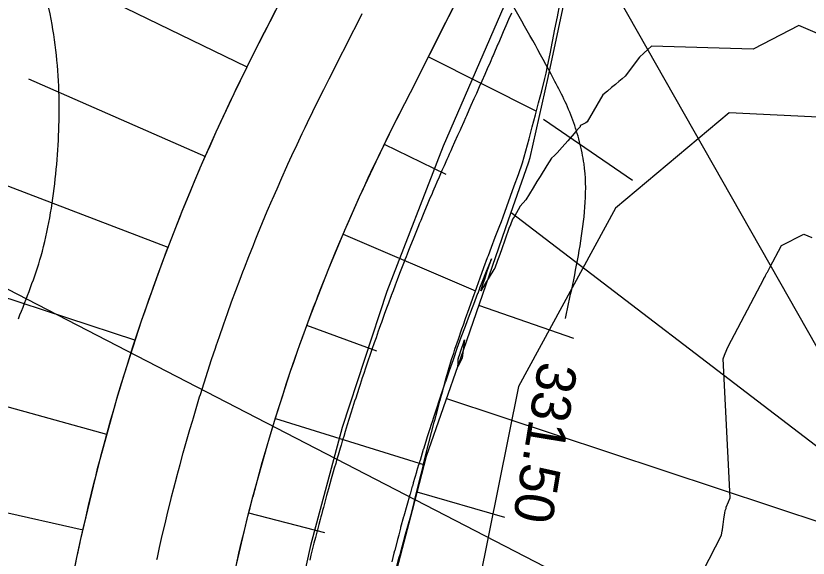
# Model space of a CAD drawing. Extents: x -564037 to -563827, y -1163561 to -1163412.
# Drawn here: x -563866.4 to -563856.32, y -1163500.35 to -1163493.46 of the extents above; entities that cross this region are included whole.
import ezdxf

# ---------------------------------------------------------------- set-up
doc = ezdxf.new("R2010")
doc.units = 0
for name, color, linetype in [('5', 7, 'Continuous'), ('Default', 7, 'Continuous'), ('Line', 7, 'Continuous'), ('Vrstva 24', 7, 'Continuous'), ('Vrstva 25', 7, 'Continuous'), ('Vrstva 26', 7, 'Continuous')]:
    doc.layers.add(name, color=color, linetype=linetype)

msp = doc.modelspace()

# ---------------------------------------------------------------- linework, layer by layer
for points in [[(-563865.785, -1163501.206), (-563865.619, -1163500.343), (-563865.574, -1163500.129), (-563865.385, -1163499.33), (-563865.317, -1163499.063), (-563865.111, -1163498.327), (-563865.015, -1163498.009), (-563864.797, -1163497.335), (-563864.669, -1163496.968), (-563864.528, -1163496.58), (-563864.443, -1163496.357), (-563864.28, -1163495.943), (-563864.051, -1163495.394), (-563863.848, -1163494.935), (-563863.62, -1163494.448), (-563863.373, -1163493.946), (-563863.165, -1163493.533), (-563862.713, -1163492.641), (-563862.262, -1163491.749), (-563861.987, -1163491.206), (-563861.81, -1163490.857), (-563861.359, -1163489.964), (-563861.279, -1163489.807)], [(-563863.62, -1163500.557), (-563863.446, -1163499.819), (-563863.383, -1163499.573), (-563863.193, -1163498.893), (-563863.104, -1163498.599), (-563862.903, -1163497.978), (-563862.785, -1163497.638), (-563862.654, -1163497.28), (-563862.576, -1163497.075), (-563862.426, -1163496.692), (-563862.214, -1163496.186), (-563862.026, -1163495.761), (-563861.817, -1163495.312), (-563861.589, -1163494.849), (-563861.38, -1163494.436), (-563860.928, -1163493.544), (-563860.477, -1163492.652), (-563860.202, -1163492.109), (-563860.026, -1163491.76), (-563859.574, -1163490.867), (-563859.495, -1163490.71)], [(-563865.645, -1163500.469), (-563865.619, -1163500.343), (-563865.613, -1163500.311), (-563865.579, -1163500.154), (-563865.574, -1163500.129), (-563865.544, -1163499.997), (-563865.508, -1163499.84), (-563865.472, -1163499.683), (-563865.434, -1163499.526), (-563865.395, -1163499.37), (-563865.385, -1163499.33), (-563865.356, -1163499.214), (-563865.317, -1163499.063), (-563865.315, -1163499.058), (-563865.274, -1163498.902), (-563865.231, -1163498.747), (-563865.188, -1163498.592), (-563865.143, -1163498.437), (-563865.111, -1163498.327), (-563865.098, -1163498.283), (-563865.052, -1163498.128), (-563865.015, -1163498.009), (-563865.004, -1163497.974), (-563864.956, -1163497.821), (-563864.907, -1163497.667), (-563864.857, -1163497.514), (-563864.806, -1163497.362), (-563864.797, -1163497.335), (-563864.754, -1163497.209), (-563864.701, -1163497.057), (-563864.669, -1163496.968), (-563864.647, -1163496.905), (-563864.592, -1163496.754), (-563864.536, -1163496.603), (-563864.48, -1163496.452), (-563864.443, -1163496.357), (-563864.422, -1163496.302), (-563864.363, -1163496.152), (-563864.304, -1163496.002), (-563864.28, -1163495.943), (-563864.243, -1163495.853), (-563864.182, -1163495.704), (-563864.12, -1163495.555), (-563864.056, -1163495.407), (-563864.051, -1163495.394), (-563863.992, -1163495.259), (-563863.927, -1163495.112), (-563863.861, -1163494.965), (-563863.848, -1163494.935), (-563863.795, -1163494.819), (-563863.727, -1163494.673), (-563863.658, -1163494.527), (-563863.62, -1163494.448), (-563863.589, -1163494.382), (-563863.518, -1163494.237), (-563863.447, -1163494.092), (-563863.374, -1163493.948), (-563863.373, -1163493.946), (-563863.305, -1163493.81), (-563863.235, -1163493.672), (-563863.165, -1163493.533), (-563863.095, -1163493.396)], [(-563863.593, -1163500.434), (-563863.56, -1163500.289), (-563863.526, -1163500.144), (-563863.491, -1163500), (-563863.455, -1163499.856), (-563863.446, -1163499.819), (-563863.419, -1163499.711), (-563863.383, -1163499.573), (-563863.381, -1163499.568), (-563863.343, -1163499.424), (-563863.304, -1163499.281), (-563863.264, -1163499.137), (-563863.223, -1163498.995), (-563863.193, -1163498.893), (-563863.181, -1163498.852), (-563863.138, -1163498.71), (-563863.104, -1163498.599), (-563863.094, -1163498.567), (-563863.05, -1163498.426), (-563863.004, -1163498.284), (-563862.958, -1163498.143), (-563862.911, -1163498.002), (-563862.903, -1163497.978), (-563862.863, -1163497.861), (-563862.814, -1163497.721), (-563862.785, -1163497.638), (-563862.764, -1163497.581), (-563862.714, -1163497.441), (-563862.662, -1163497.301), (-563862.61, -1163497.162), (-563862.576, -1163497.075), (-563862.557, -1163497.023), (-563862.503, -1163496.885), (-563862.448, -1163496.747), (-563862.426, -1163496.692), (-563862.392, -1163496.609), (-563862.335, -1163496.472), (-563862.278, -1163496.334), (-563862.219, -1163496.198), (-563862.214, -1163496.186), (-563862.16, -1163496.061), (-563862.1, -1163495.925), (-563862.039, -1163495.79), (-563862.026, -1163495.761), (-563861.978, -1163495.654), (-563861.915, -1163495.52), (-563861.852, -1163495.385), (-563861.817, -1163495.312), (-563861.787, -1163495.251), (-563861.722, -1163495.117), (-563861.657, -1163494.984), (-563861.59, -1163494.851), (-563861.589, -1163494.849), (-563861.52, -1163494.713), (-563861.45, -1163494.575), (-563861.38, -1163494.436), (-563861.31, -1163494.299), (-563861.24, -1163494.16), (-563861.17, -1163494.022), (-563861.1, -1163493.884), (-563861.031, -1163493.746), (-563860.961, -1163493.608), (-563860.928, -1163493.544), (-563860.891, -1163493.47), (-563860.821, -1163493.331)], [(-563861.556, -1163500.472), (-563861.521, -1163500.34), (-563861.512, -1163500.306), (-563861.485, -1163500.208), (-563861.45, -1163500.081), (-563861.449, -1163500.077), (-563861.412, -1163499.946), (-563861.374, -1163499.815), (-563861.34, -1163499.683), (-563861.309, -1163499.55), (-563861.286, -1163499.455), (-563861.277, -1163499.417), (-563861.245, -1163499.285), (-563861.219, -1163499.182), (-563861.212, -1163499.152), (-563861.179, -1163499.019), (-563861.145, -1163498.887), (-563861.111, -1163498.754), (-563861.076, -1163498.622), (-563861.07, -1163498.599), (-563861.041, -1163498.489), (-563861.005, -1163498.357), (-563860.984, -1163498.279), (-563860.969, -1163498.225), (-563860.932, -1163498.092), (-563860.895, -1163497.96), (-563860.857, -1163497.828), (-563860.83, -1163497.746), (-563860.814, -1163497.698), (-563860.769, -1163497.568), (-563860.725, -1163497.438), (-563860.707, -1163497.386), (-563860.68, -1163497.308), (-563860.634, -1163497.179), (-563860.588, -1163497.049), (-563860.541, -1163496.92), (-563860.537, -1163496.909), (-563860.494, -1163496.791), (-563860.446, -1163496.661), (-563860.398, -1163496.532), (-563860.388, -1163496.505), (-563860.35, -1163496.403), (-563860.301, -1163496.274), (-563860.251, -1163496.146), (-563860.224, -1163496.075), (-563860.201, -1163496.017), (-563860.155, -1163495.886), (-563860.109, -1163495.755), (-563860.062, -1163495.624), (-563860.061, -1163495.622), (-563860.008, -1163495.478), (-563859.954, -1163495.332), (-563859.913, -1163495.179), (-563859.872, -1163495.026), (-563859.831, -1163494.873), (-563859.791, -1163494.72), (-563859.751, -1163494.567), (-563859.71, -1163494.414), (-563859.671, -1163494.26), (-563859.655, -1163494.189), (-563859.637, -1163494.104), (-563859.605, -1163493.946), (-563859.573, -1163493.789), (-563859.542, -1163493.631), (-563859.51, -1163493.474), (-563859.479, -1163493.316)], [(-563864.602, -1163500.367), (-563864.597, -1163500.343), (-563864.568, -1163500.215), (-563864.534, -1163500.064), (-563864.499, -1163499.914), (-563864.462, -1163499.763), (-563864.425, -1163499.613), (-563864.416, -1163499.574), (-563864.387, -1163499.463), (-563864.35, -1163499.318), (-563864.348, -1163499.313), (-563864.308, -1163499.163), (-563864.267, -1163499.014), (-563864.226, -1163498.865), (-563864.183, -1163498.716), (-563864.152, -1163498.61), (-563864.139, -1163498.567), (-563864.095, -1163498.419), (-563864.06, -1163498.304), (-563864.049, -1163498.271), (-563864.003, -1163498.123), (-563863.956, -1163497.976), (-563863.908, -1163497.829), (-563863.858, -1163497.682), (-563863.85, -1163497.656), (-563863.808, -1163497.535), (-563863.757, -1163497.389), (-563863.727, -1163497.303), (-563863.706, -1163497.243), (-563863.653, -1163497.097), (-563863.599, -1163496.952), (-563863.545, -1163496.807), (-563863.51, -1163496.716), (-563863.489, -1163496.663), (-563863.433, -1163496.518), (-563863.376, -1163496.374), (-563863.353, -1163496.317), (-563863.318, -1163496.231), (-563863.259, -1163496.088), (-563863.199, -1163495.945), (-563863.138, -1163495.802), (-563863.133, -1163495.79), (-563863.076, -1163495.66), (-563863.014, -1163495.519), (-563862.95, -1163495.377), (-563862.937, -1163495.348), (-563862.886, -1163495.237), (-563862.821, -1163495.096), (-563862.755, -1163494.956), (-563862.719, -1163494.88), (-563862.688, -1163494.816), (-563862.62, -1163494.677), (-563862.552, -1163494.538), (-563862.482, -1163494.4), (-563862.481, -1163494.397), (-563862.412, -1163494.262), (-563862.342, -1163494.123), (-563862.272, -1163493.985), (-563862.202, -1163493.847), (-563862.133, -1163493.709), (-563862.063, -1163493.571), (-563861.993, -1163493.433)], [(-563855.435, -1163494.017), (-563856.443, -1163493.586), (-563857.024, -1163493.885), (-563858.314, -1163493.847), (-563858.363, -1163493.892), (-563858.414, -1163493.938), (-563858.468, -1163493.988), (-563858.651, -1163494.229), (-563858.689, -1163494.261), (-563858.73, -1163494.296), (-563858.769, -1163494.329), (-563858.774, -1163494.333), (-563858.822, -1163494.374), (-563858.875, -1163494.418), (-563858.933, -1163494.467), (-563859.131, -1163494.809), (-563859.152, -1163494.82), (-563859.176, -1163494.834), (-563859.201, -1163494.847), (-563859.208, -1163494.851), (-563859.22, -1163494.858), (-563859.223, -1163494.872), (-563859.239, -1163494.89), (-563859.277, -1163494.933), (-563859.323, -1163494.985), (-563859.38, -1163495.049), (-563859.452, -1163495.13), (-563859.516, -1163495.202), (-563859.532, -1163495.22), (-563859.55, -1163495.236), (-563859.588, -1163495.27), (-563859.647, -1163495.365), (-563859.731, -1163495.502), (-563859.772, -1163495.568), (-563859.819, -1163495.646), (-563859.914, -1163495.799), (-563859.984, -1163495.881), (-563860.055, -1163496.01), (-563860.068, -1163496.027), (-563860.083, -1163496.044), (-563860.108, -1163496.116), (-563860.127, -1163496.166), (-563860.175, -1163496.301), (-563860.224, -1163496.436), (-563860.257, -1163496.528), (-563860.272, -1163496.571), (-563860.308, -1163496.67), (-563860.318, -1163496.685), (-563860.486, -1163496.955), (-563860.463, -1163496.887), (-563860.451, -1163496.852), (-563860.436, -1163496.807), (-563860.403, -1163496.707), (-563860.359, -1163496.574), (-563860.358, -1163496.571), (-563860.351, -1163496.551), (-563860.359, -1163496.571), (-563860.359, -1163496.571), (-563860.416, -1163496.71), (-563860.416, -1163496.71), (-563860.471, -1163496.849), (-563860.471, -1163496.849), (-563860.5, -1163496.924), (-563860.501, -1163496.925), (-563860.525, -1163496.989), (-563860.526, -1163496.989), (-563860.579, -1163497.128), (-563860.58, -1163497.129), (-563860.633, -1163497.268), (-563860.633, -1163497.269), (-563860.681, -1163497.397), (-563860.681, -1163497.397), (-563860.685, -1163497.409), (-563860.685, -1163497.409), (-563860.737, -1163497.549), (-563860.737, -1163497.55), (-563860.788, -1163497.69), (-563860.788, -1163497.69), (-563860.811, -1163497.753), (-563860.811, -1163497.754), (-563860.838, -1163497.831), (-563860.838, -1163497.832), (-563860.888, -1163497.972), (-563860.888, -1163497.973), (-563860.936, -1163498.113), (-563860.937, -1163498.115), (-563860.985, -1163498.255), (-563860.985, -1163498.255), (-563860.992, -1163498.276), (-563860.993, -1163498.279), (-563861.032, -1163498.397), (-563861.033, -1163498.4), (-563861.079, -1163498.539), (-563861.079, -1163498.54), (-563861.095, -1163498.59), (-563861.096, -1163498.593), (-563861.125, -1163498.681), (-563861.126, -1163498.685), (-563861.17, -1163498.824), (-563861.171, -1163498.828), (-563861.214, -1163498.966), (-563861.216, -1163498.971), (-563861.258, -1163499.109), (-563861.259, -1163499.111), (-563861.275, -1163499.164), (-563861.276, -1163499.168), (-563861.301, -1163499.252), (-563861.303, -1163499.258), (-563861.343, -1163499.396), (-563861.344, -1163499.397), (-563861.355, -1163499.435), (-563861.356, -1163499.439), (-563861.385, -1163499.539), (-563861.387, -1163499.546), (-563861.426, -1163499.683), (-563861.464, -1163499.82), (-563861.466, -1163499.827), (-563861.504, -1163499.964), (-563861.505, -1163499.971), (-563861.528, -1163500.056), (-563861.529, -1163500.061), (-563861.543, -1163500.113), (-563861.544, -1163500.116), (-563861.58, -1163500.254), (-563861.582, -1163500.26), (-563861.589, -1163500.286), (-563861.589, -1163500.287), (-563861.618, -1163500.4)], [(-563851.082, -1163505.728), (-563849.948, -1163501.531), (-563849.628, -1163500.347), (-563850.165, -1163499.681), (-563852.128, -1163495.731), (-563853.44, -1163495.48), (-563855.061, -1163494.806), (-563857.328, -1163494.696), (-563858.771, -1163495.906), (-563860.007, -1163498.17), (-563860.512, -1163500.673), (-563860.896, -1163502.23)], [(-563859.058, -1163503.231), (-563857.424, -1163500.06), (-563857.416, -1163500.003), (-563857.414, -1163499.991), (-563857.404, -1163499.921), (-563857.401, -1163499.894), (-563857.395, -1163499.851), (-563857.385, -1163499.781), (-563857.38, -1163499.748), (-563857.366, -1163499.72), (-563857.367, -1163499.709), (-563857.367, -1163499.705), (-563857.337, -1163499.637), (-563857.314, -1163499.585), (-563857.403, -1163497.819), (-563857.398, -1163497.805), (-563857.377, -1163497.753), (-563857.365, -1163497.722), (-563857.357, -1163497.702), (-563857.342, -1163497.665), (-563856.887, -1163496.804), (-563856.887, -1163496.803), (-563856.885, -1163496.799), (-563856.875, -1163496.781), (-563856.866, -1163496.763), (-563856.86, -1163496.752), (-563856.856, -1163496.745), (-563856.847, -1163496.728), (-563856.842, -1163496.718), (-563856.812, -1163496.661), (-563856.664, -1163496.381), (-563856.379, -1163496.234), (-563856.277, -1163496.278)]]:
    msp.add_lwpolyline(points)
for points in [[(-563864.657, -1163510.241), (-563863.634, -1163509.902), (-563862.371, -1163510.364), (-563856.258, -1163509.872), (-563849.971, -1163509.495), (-563846.657, -1163503.058), (-563846.814, -1163502.626), (-563847.162, -1163502.341), (-563848.492, -1163499.244), (-563850.901, -1163494.112), (-563854.114, -1163491.532), (-563858.451, -1163490.091), (-563858.61, -1163489.95), (-563858.72, -1163489.955), (-563860.965, -1163495.118), (-563861.68, -1163496.963), (-563862.247, -1163498.693), (-563862.652, -1163500.191), (-563862.88, -1163501.229), (-563863.177, -1163502.77), (-563863.416, -1163504.013), (-563864.472, -1163509.23)], [(-563860.775, -1163497.874), (-563860.774, -1163497.856), (-563860.772, -1163497.824), (-563860.764, -1163497.796), (-563860.757, -1163497.773), (-563860.738, -1163497.717), (-563860.717, -1163497.654), (-563860.715, -1163497.648), (-563860.693, -1163497.58), (-563860.72, -1163497.806), (-563860.723, -1163497.812), (-563860.778, -1163497.915)]]:
    msp.add_lwpolyline(points, close=True)
at = {"layer": '5'}
msp.add_line((-563871.424, -1163494.398), (-563841.172, -1163509.993), dxfattribs=at)
at = {"layer": 'Default'}
for points in [[(-563850.252, -1163510.208), (-563856.616, -1163510.499), (-563858.417, -1163510.582), (-563858.622, -1163510.591), (-563858.765, -1163510.598), (-563862.588, -1163510.773), (-563864.593, -1163510.11), (-563864.305, -1163509.276), (-563863.831, -1163507.903), (-563863.009, -1163505.523), (-563862.206, -1163502.984), (-563862.121, -1163502.658), (-563861.871, -1163501.708), (-563861.355, -1163499.743), (-563861.175, -1163499.057), (-563860.744, -1163497.818), (-563860.132, -1163496.055), (-563859.88, -1163495.331), (-563859.856, -1163495.261), (-563859.628, -1163494.247), (-563858.554, -1163489.211), (-563856.89, -1163488.106), (-563853.44, -1163488.662)], [(-563860.096, -1163493.43), (-563860.131, -1163493.511), (-563860.165, -1163493.588), (-563860.199, -1163493.668), (-563860.227, -1163493.731), (-563860.26, -1163493.809), (-563860.267, -1163493.824), (-563860.302, -1163493.904), (-563860.329, -1163493.966), (-563860.336, -1163493.981), (-563860.368, -1163494.054), (-563860.404, -1163494.136), (-563860.436, -1163494.209), (-563860.473, -1163494.292), (-563860.504, -1163494.364), (-563860.541, -1163494.448), (-563860.573, -1163494.519), (-563860.61, -1163494.603), (-563860.637, -1163494.663), (-563860.669, -1163494.735), (-563860.68, -1163494.758), (-563860.702, -1163494.809), (-563860.74, -1163494.894), (-563860.749, -1163494.914), (-563860.78, -1163494.983), (-563860.819, -1163495.068), (-563860.85, -1163495.137), (-563860.867, -1163495.176), (-563860.887, -1163495.221), (-563860.901, -1163495.252), (-563860.916, -1163495.286), (-563860.953, -1163495.368), (-563860.98, -1163495.429), (-563861.016, -1163495.512), (-563861.043, -1163495.574), (-563861.065, -1163495.625), (-563861.082, -1163495.664), (-563861.095, -1163495.695), (-563861.105, -1163495.718), (-563861.14, -1163495.8), (-563861.166, -1163495.862), (-563861.2, -1163495.945), (-563861.226, -1163496.007), (-563861.249, -1163496.064), (-563861.267, -1163496.106), (-563861.278, -1163496.132), (-563861.286, -1163496.152), (-563861.319, -1163496.235), (-563861.345, -1163496.298), (-563861.378, -1163496.38), (-563861.403, -1163496.443), (-563861.42, -1163496.488), (-563861.434, -1163496.522), (-563861.449, -1163496.56), (-563861.46, -1163496.589), (-563861.492, -1163496.672), (-563861.517, -1163496.735), (-563861.548, -1163496.818), (-563861.573, -1163496.882), (-563861.601, -1163496.957), (-563861.623, -1163497.016), (-563861.626, -1163497.023), (-563861.628, -1163497.028), (-563861.658, -1163497.111), (-563861.682, -1163497.175), (-563861.712, -1163497.258), (-563861.736, -1163497.322), (-563861.749, -1163497.36), (-563861.759, -1163497.389), (-563861.776, -1163497.434), (-563861.788, -1163497.47), (-563861.817, -1163497.552), (-563861.84, -1163497.617), (-563861.869, -1163497.7), (-563861.891, -1163497.765), (-563861.92, -1163497.848), (-563861.942, -1163497.913), (-563861.946, -1163497.926), (-563861.949, -1163497.936), (-563861.973, -1163498.006), (-563861.992, -1163498.062), (-563862.019, -1163498.145), (-563862.041, -1163498.21), (-563862.05, -1163498.24), (-563862.058, -1163498.264), (-563862.075, -1163498.318), (-563862.089, -1163498.359), (-563862.115, -1163498.443), (-563862.136, -1163498.508), (-563862.162, -1163498.592), (-563862.183, -1163498.657), (-563862.209, -1163498.742), (-563862.228, -1163498.807), (-563862.238, -1163498.839), (-563862.246, -1163498.864), (-563862.262, -1163498.917), (-563862.274, -1163498.956), (-563862.299, -1163499.042), (-563862.318, -1163499.106), (-563862.325, -1163499.13), (-563862.33, -1163499.147), (-563862.348, -1163499.21), (-563862.361, -1163499.256), (-563862.386, -1163499.342), (-563862.404, -1163499.407), (-563862.422, -1163499.471), (-563862.446, -1163499.557), (-563862.464, -1163499.622), (-563862.487, -1163499.708), (-563862.498, -1163499.748), (-563862.512, -1163499.802), (-563862.519, -1163499.826), (-563862.528, -1163499.859), (-563862.545, -1163499.924), (-563862.567, -1163500.01), (-563862.57, -1163500.022), (-563862.574, -1163500.038), (-563862.588, -1163500.091), (-563862.606, -1163500.162), (-563862.623, -1163500.227), (-563862.644, -1163500.313), (-563862.66, -1163500.379)]]:
    msp.add_lwpolyline(points, dxfattribs=at)
at = {"layer": 'Line'}
for p, q in [((-563863.457, -1163494.115), (-563867.593, -1163492.106)), ((-563854.949, -1163499.897), (-563859.159, -1163492.49)), ((-563861.15, -1163493.982), (-563859.778, -1163494.673)), ((-563866.237, -1163494.262), (-563863.986, -1163495.248)), ((-563864.459, -1163496.404), (-563869.35, -1163494.536)), ((-563858.558, -1163495.555), (-563859.689, -1163494.781)), ((-563860.927, -1163495.476), (-563861.711, -1163495.099)), ((-563860.099, -1163495.962), (-563854.949, -1163499.897)), ((-563862.233, -1163496.234), (-563860.554, -1163496.954)), ((-563867.464, -1163496.734), (-563864.877, -1163497.582)), ((-563859.304, -1163497.561), (-563860.509, -1163497.143)), ((-563865.238, -1163498.779), (-563870.41, -1163497.354)), ((-563861.808, -1163497.722), (-563862.695, -1163497.396)), ((-563860.92, -1163498.323), (-563855.149, -1163500.234)), ((-563863.096, -1163498.579), (-563861.215, -1163499.163)), ((-563868.019, -1163499.435), (-563865.541, -1163499.991)), ((-563860.18, -1163499.837), (-563861.295, -1163499.515)), ((-563862.469, -1163500.028), (-563863.435, -1163499.782))]:
    msp.add_line(p, q, dxfattribs=at)
at = {"layer": 'Vrstva 24'}
for points in [[(-563834.56, -1163494.639), (-563836.366, -1163491.682), (-563837.263, -1163490.402), (-563838.091, -1163489.323), (-563838.932, -1163488.255), (-563840.679, -1163486.176), (-563843.599, -1163482.931), (-563845.377, -1163480.993), (-563847.69, -1163478.523), (-563848.871, -1163477.312), (-563850.082, -1163476.13), (-563853.183, -1163473.259), (-563856.324, -1163470.434), (-563856.74, -1163470.064), (-563856.896, -1163469.927), (-563857.179, -1163469.672), (-563858.782, -1163468.194), (-563860.374, -1163466.704), (-563861.969, -1163465.217), (-563862.806, -1163464.448)], [(-563866.364, -1163497.311), (-563866.075, -1163496.511), (-563865.895, -1163495.533), (-563865.845, -1163494.553), (-563865.947, -1163493.507), (-563866.272, -1163492.388), (-563866.563, -1163491.699), (-563866.868, -1163491.02), (-563867.192, -1163490.352), (-563867.536, -1163489.691), (-563869.125, -1163486.92), (-563869.85, -1163485.772), (-563870.624, -1163484.653), (-563871.666, -1163483.346), (-563872.824, -1163482.142), (-563874.562, -1163480.618), (-563875.472, -1163479.893), (-563878.363, -1163477.556), (-563882.755, -1163474.046), (-563884.234, -1163472.969), (-563885.61, -1163472.026), (-563886.998, -1163471.1), (-563889.83, -1163469.34), (-563892.347, -1163467.891)], [(-563852.947, -1163500.287), (-563852.983, -1163499.934), (-563853.278, -1163497.907), (-563853.324, -1163497.501), (-563853.384, -1163496.604), (-563853.408, -1163496.155), (-563853.449, -1163495.707), (-563853.76, -1163494.797), (-563854.364, -1163493.737), (-563856.816, -1163489.636), (-563859.313, -1163485.439), (-563859.915, -1163484.694), (-563860.397, -1163484.207), (-563862.509, -1163482.09), (-563867.011, -1163477.664), (-563868.116, -1163476.702), (-563871.116, -1163474.41), (-563872.986, -1163473.06), (-563873.689, -1163472.566), (-563878.103, -1163469.411), (-563878.316, -1163469.26)], [(-563840.258, -1163509.873), (-563839.896, -1163508.143), (-563839.904, -1163507.091), (-563840.452, -1163504.683), (-563840.841, -1163503.06), (-563841.044, -1163502.221), (-563841.512, -1163500.521), (-563841.78, -1163499.679), (-563842.064, -1163498.842), (-563842.395, -1163498.068), (-563843.845, -1163495.39), (-563845.853, -1163491.78), (-563846.807, -1163490.032), (-563847.876, -1163488.404), (-563852.123, -1163483.19), (-563853.868, -1163481.341), (-563857.18, -1163478.245), (-563858.504, -1163477.011), (-563860.386, -1163475.26)]]:
    msp.add_spline(points, degree=3, dxfattribs=at)
at = {"layer": 'Vrstva 26'}
for points in [[(-563838.029, -1163497.163), (-563838.58, -1163496.19), (-563840.28, -1163493.165), (-563841.199, -1163491.578), (-563841.674, -1163490.793), (-563842.159, -1163490.013), (-563843.649, -1163487.993), (-563844.702, -1163486.757), (-563850.461, -1163480.038), (-563851.089, -1163479.371), (-563851.956, -1163478.574), (-563857.613, -1163473.501), (-563859.731, -1163471.636), (-563864.022, -1163468.083), (-563864.562, -1163467.631), (-563865.045, -1163467.216), (-563865.679, -1163466.68)], [(-563859.41, -1163497.306), (-563859.213, -1163496.32), (-563859.173, -1163495.343), (-563859.23, -1163495.062), (-563859.315, -1163494.786), (-563859.559, -1163494.264), (-563860.664, -1163492.33), (-563861.767, -1163490.395), (-563863.612, -1163487.077), (-563864.619, -1163485.435), (-563865.167, -1163484.642), (-563865.744, -1163483.864), (-563868.01, -1163481.46), (-563871.348, -1163478.665), (-563874.529, -1163476.131), (-563879.25, -1163472.365), (-563881.038, -1163471.025), (-563881.839, -1163470.479), (-563883.542, -1163469.415), (-563886.341, -1163467.718)], [(-563846.143, -1163505.119), (-563846.16, -1163504.298), (-563846.784, -1163499.435), (-563846.859, -1163499.141), (-563847.15, -1163498.47), (-563847.685, -1163497.291), (-563847.809, -1163497.032), (-563850.257, -1163492.396), (-563853.06, -1163487.093), (-563853.131, -1163486.997), (-563856.933, -1163483.04), (-563859.434, -1163480.56), (-563863.484, -1163476.533), (-563865.168, -1163474.917), (-563866.123, -1163474.143), (-563868.988, -1163472.112)]]:
    msp.add_spline(points, degree=3, dxfattribs=at)

# ---------------------------------------------------------------- texts
at = {"layer": 'Vrstva 25'}
msp.add_text('331.50', height=0.5, rotation=260.6689, dxfattribs=at).set_placement((-563859.746, -1163497.839))

doc.saveas('drawing.dxf')
